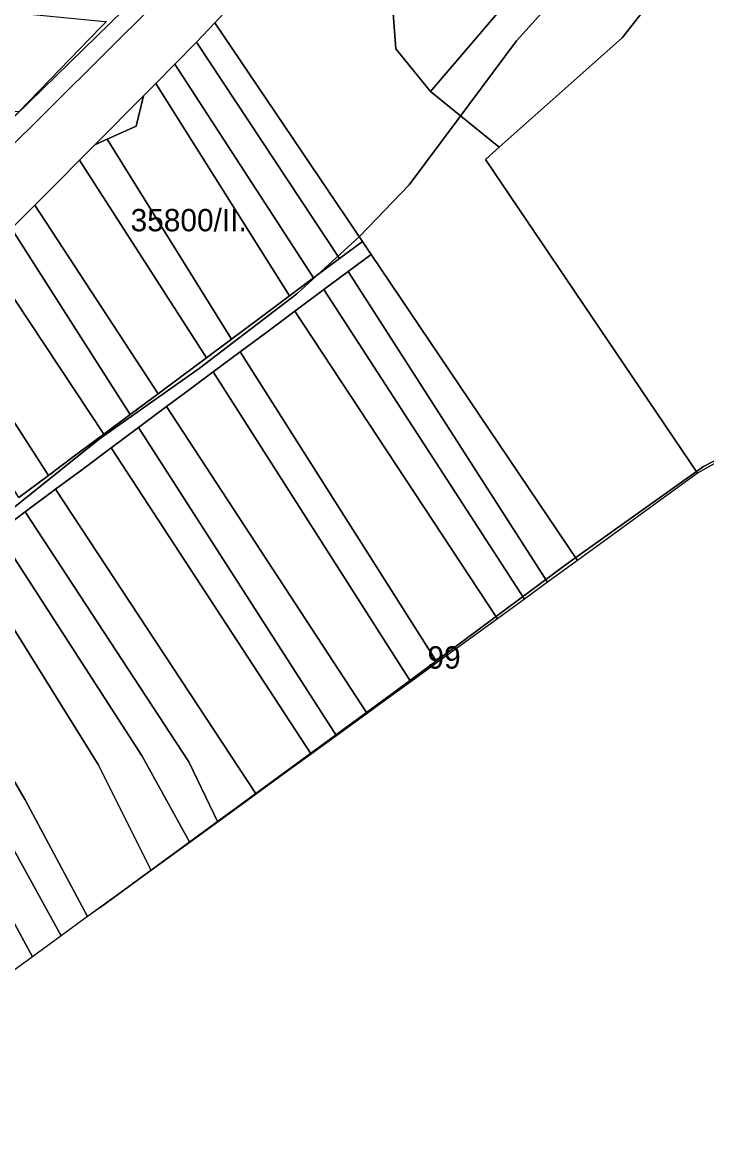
# Model space of a CAD drawing. Extents: x -535894 to -532834, y -1165802 to -1163645.
# Drawn here: x -534096.6 to -533943.2, y -1165431.5 to -1165184 of the extents above; entities that cross this region are included whole.
import ezdxf

# ---------------------------------------------------------------- set-up
doc = ezdxf.new("R2010")
doc.units = 0
for name, color, linetype in [('95560013', 7, 'Continuous'), ('95610013', 7, 'Continuous'), ('95630013', 7, 'Continuous'), ('95640013', 7, 'Continuous'), ('95660013', 7, 'Continuous')]:
    doc.layers.add(name, color=color, linetype=linetype)

msp = doc.modelspace()

# ---------------------------------------------------------------- linework, layer by layer
at = {"layer": '95560013'}
for points in [[(-534196.09, -1165177.34), (-534144.9, -1165178.54), (-534107.5, -1165181.08), (-534103.37, -1165181.48), (-534078.8, -1165183.83), (-534077.66, -1165183.91), (-534078.91, -1165185.19), (-534097.29, -1165204.09), (-534111.65, -1165203.25), (-534176.94, -1165199.42), (-534196.74, -1165197.75)], [(-534053.42, -1165184.18), (-534020.37, -1165233.16), (-534025.49, -1165236.98), (-534057.5, -1165188.56)], [(-534057.5, -1165188.56), (-534025.49, -1165236.98), (-534031.31, -1165241.3), (-534062.36, -1165193.44)], [(-534062.36, -1165193.44), (-534031.31, -1165241.3), (-534036.68, -1165245.31), (-534066.63, -1165197.75)], [(-534066.63, -1165197.75), (-534036.68, -1165245.31), (-534043.59, -1165250.46), (-534049.71, -1165255.01), (-534077.55, -1165210.26), (-534071.03, -1165207.31), (-534069.42, -1165200.54)], [(-534071.03, -1165207.31), (-534077.55, -1165210.26), (-534080.31, -1165211.51), (-534069.42, -1165200.54)], [(-534080.31, -1165211.51), (-534077.55, -1165210.26), (-534049.71, -1165255.01), (-534055.31, -1165259.18), (-534083.69, -1165214.91)], [(-534083.69, -1165214.91), (-534055.31, -1165259.18), (-534060.78, -1165263.26), (-534066.12, -1165267.23), (-534093.73, -1165225.02), (-534088.44, -1165219.7)], [(-534093.73, -1165225.02), (-534066.12, -1165267.23), (-534072.4, -1165271.89), (-534098.91, -1165230.23)], [(-534098.91, -1165230.23), (-534072.4, -1165271.89), (-534078.3, -1165276.29), (-534105.03, -1165235.88)], [(-534105.03, -1165235.88), (-534078.3, -1165276.29), (-534085.13, -1165281.37), (-534090.65, -1165285.49), (-534116.12, -1165246.09), (-534110.88, -1165241.27)], [(-534116.12, -1165246.09), (-534090.65, -1165285.49), (-534097.28, -1165290.43), (-534121.92, -1165251.44)]]:
    msp.add_lwpolyline(points, close=True, dxfattribs=at)
at = {"layer": '95610013'}
for points in [[(-533962.53, -1165085.32), (-533934.45, -1165116.87), (-533940.8, -1165124.3), (-534005.15, -1165199.61), (-534012.92, -1165190.05), (-534014.17, -1165173.12), (-534019.14, -1165162.52), (-534024.54, -1165159.35), (-534021.42, -1165157.14), (-534022.96, -1165151.54), (-534010.91, -1165138.64), (-533976.02, -1165098.2)], [(-533940.8, -1165124.3), (-533927.13, -1165137.47), (-533922.67, -1165144.99), (-533928.42, -1165147.92), (-533942.82, -1165162.9), (-533962.19, -1165187.57), (-533989.71, -1165212.03), (-534005.15, -1165199.61)], [(-534024.54, -1165159.35), (-534019.14, -1165162.52), (-534014.17, -1165173.12), (-534012.92, -1165190.05), (-534005.15, -1165199.61), (-533989.71, -1165212.03), (-533992.77, -1165214.76), (-533945.33, -1165285.03), (-533972.2, -1165304.55), (-534018.44, -1165236.03), (-534020.37, -1165233.16), (-534053.42, -1165184.18), (-534033.26, -1165162.58), (-534030.52, -1165163.57)], [(-533962.19, -1165187.57), (-533942.82, -1165162.9), (-533914.6, -1165207.64), (-533885.93, -1165251.42), (-533945.33, -1165285.03), (-533992.77, -1165214.76), (-533989.71, -1165212.03)], [(-534018.44, -1165236.03), (-533972.2, -1165304.55), (-533978.9, -1165309.42), (-534023.58, -1165239.87)], [(-534023.58, -1165239.87), (-533978.9, -1165309.42), (-533984.1, -1165313.19), (-534028.98, -1165243.88)], [(-534028.98, -1165243.88), (-533984.1, -1165313.19), (-533990.15, -1165317.59), (-534035.47, -1165248.71)], [(-534035.47, -1165248.71), (-533990.15, -1165317.59), (-533996.63, -1165322.3), (-534003.61, -1165327.37), (-534047.73, -1165257.84), (-534041.8, -1165253.42)], [(-534047.73, -1165257.84), (-534003.61, -1165327.37), (-534009.54, -1165331.68), (-534053.75, -1165262.31)], [(-534053.75, -1165262.31), (-534009.54, -1165331.68), (-534014.32, -1165335.17), (-534019.31, -1165338.8), (-534064.21, -1165270.09), (-534058.84, -1165266.1)], [(-534064.21, -1165270.09), (-534019.31, -1165338.8), (-534026.18, -1165343.78), (-534070.53, -1165274.8)], [(-534070.53, -1165274.8), (-534026.18, -1165343.78), (-534031.82, -1165347.88), (-534076.64, -1165279.34)], [(-534076.64, -1165279.34), (-534031.82, -1165347.88), (-534037.71, -1165352.16), (-534044.14, -1165356.83), (-534089.06, -1165288.58), (-534083, -1165284.08)], [(-534089.06, -1165288.58), (-534044.14, -1165356.83), (-534052.73, -1165363.08), (-534059.26, -1165349.61), (-534095.86, -1165293.64)], [(-534095.86, -1165293.64), (-534059.26, -1165349.61), (-534052.73, -1165363.08), (-534059.04, -1165367.66), (-534069.65, -1165348.37), (-534102.06, -1165298.25)], [(-534102.06, -1165298.25), (-534069.65, -1165348.37), (-534059.04, -1165367.66), (-534067.65, -1165373.91), (-534079.55, -1165350.17), (-534108.76, -1165303.24)], [(-534108.76, -1165303.24), (-534079.55, -1165350.17), (-534067.65, -1165373.91), (-534075.22, -1165379.41), (-534081.89, -1165384.25), (-534095.85, -1165358.13), (-534121.89, -1165313.8), (-534115.44, -1165308.22)], [(-534128.01, -1165319.11), (-534121.89, -1165313.8), (-534095.85, -1165358.13), (-534081.89, -1165384.25), (-534087.82, -1165388.56), (-534103.02, -1165361.05)], [(-534134.26, -1165324.52), (-534128.01, -1165319.11), (-534103.02, -1165361.05), (-534087.82, -1165388.56), (-534094.23, -1165393.22), (-534108.57, -1165366.89)], [(-534140.55, -1165329.98), (-534134.26, -1165324.52), (-534108.57, -1165366.89), (-534094.23, -1165393.22), (-534100.32, -1165397.66)]]:
    msp.add_lwpolyline(points, close=True, dxfattribs=at)
at = {"layer": '95630013'}
for points in [[(-534033.26, -1165162.58), (-534053.42, -1165184.18), (-534057.5, -1165188.56), (-534062.36, -1165193.44), (-534066.63, -1165197.75), (-534069.42, -1165200.54), (-534080.31, -1165211.51), (-534083.69, -1165214.91), (-534088.44, -1165219.7), (-534093.73, -1165225.02), (-534098.91, -1165230.23)], [(-534136.8, -1165249.37), (-534066.72, -1165179.82)]]:
    msp.add_lwpolyline(points, dxfattribs=at)
at = {"layer": '95640013'}
for points in [[(-534066.72, -1165179.82), (-534136.8, -1165249.37), (-534194.29, -1165306.12), (-534200.89, -1165312.54), (-534205.31, -1165316.61), (-534215.14, -1165313.24), (-534244.31, -1165303.28), (-534241.33, -1165297.17), (-534240.88, -1165296.25), (-534228.15, -1165300.5), (-534203.98, -1165308.56), (-534201.96, -1165306.58), (-534145.83, -1165251.25), (-534131.84, -1165237.61), (-534110.19, -1165216.6), (-534097.29, -1165204.09), (-534078.91, -1165185.19), (-534077.66, -1165183.91)], [(-534097.28, -1165290.43), (-534090.65, -1165285.49), (-534085.13, -1165281.37), (-534078.3, -1165276.29), (-534072.4, -1165271.89), (-534066.12, -1165267.23), (-534060.78, -1165263.26), (-534055.31, -1165259.18), (-534049.71, -1165255.01), (-534043.59, -1165250.46), (-534036.68, -1165245.31), (-534031.31, -1165241.3), (-534025.49, -1165236.98), (-534020.37, -1165233.16), (-534018.44, -1165236.03), (-534023.58, -1165239.87), (-534028.98, -1165243.88), (-534035.47, -1165248.71), (-534041.8, -1165253.42), (-534047.73, -1165257.84), (-534053.75, -1165262.31), (-534058.84, -1165266.1), (-534064.21, -1165270.09), (-534070.53, -1165274.8), (-534076.64, -1165279.34), (-534083, -1165284.08), (-534089.06, -1165288.58), (-534095.86, -1165293.64), (-534102.06, -1165298.25)]]:
    msp.add_lwpolyline(points, dxfattribs=at)
at = {"layer": '95660013'}
for points in [[(-534504, -1165364.91), (-534479.15, -1165348.82), (-534459.071, -1165335.819), (-534440.92, -1165327.96), (-534400.789, -1165317.92), (-534366.86, -1165313.619), (-534340.91, -1165310.331), (-534288.01, -1165303.627), (-534259.201, -1165299.977), (-534247.08, -1165300.4), (-534235.298, -1165303.278), (-534220.661, -1165306.853), (-534211.72, -1165306.77), (-534205.67, -1165305.18), (-534198.42, -1165301.519), (-534191.96, -1165296.599), (-534183.05, -1165287.34), (-534159.56, -1165262.93), (-534128.66, -1165234.701), (-534052.52, -1165160.48), (-533990.56, -1165093.1), (-533942.78, -1165048.02)], [(-534052.52, -1165160.48), (-534128.66, -1165234.701)], [(-534105.4, -1165298.17), (-534079.332, -1165277.377), (-534075.955, -1165274.993), (-534056.9, -1165261.54), (-534035.084, -1165244.865), (-534020.91, -1165231.99), (-534009.91, -1165220.44), (-533999.16, -1165206.031), (-533985.872, -1165188.218), (-533970.41, -1165171.07)], [(-533970.41, -1165171.07), (-533985.872, -1165188.218), (-533999.16, -1165206.031), (-534009.91, -1165220.44), (-534020.91, -1165231.99), (-534035.084, -1165244.865), (-534056.9, -1165261.54), (-534075.955, -1165274.993), (-534079.332, -1165277.377), (-534105.4, -1165298.17)], [(-533928.089, -1165275.274), (-533943.99, -1165283.5), (-533974.66, -1165305.36), (-534013.02, -1165333.89), (-534079.092, -1165382.22), (-534081.89, -1165384.25), (-534087.82, -1165388.56), (-534094.23, -1165393.22), (-534100.32, -1165397.66), (-534105.93, -1165402.64), (-534112, -1165409.73), (-534115, -1165414.12), (-534119.41, -1165420.59), (-534123.86, -1165427.13), (-534126.75, -1165433.55)]]:
    msp.add_lwpolyline(points, dxfattribs=at)
msp.add_lwpolyline([(-534075.22, -1165379.41), (-534079.092, -1165382.22), (-534013.02, -1165333.89), (-533974.66, -1165305.36), (-533943.99, -1165283.5), (-533928.089, -1165275.274), (-533945.33, -1165285.03), (-533972.2, -1165304.55), (-533978.9, -1165309.42), (-533984.1, -1165313.19), (-533990.15, -1165317.59), (-533996.63, -1165322.3), (-534003.61, -1165327.37), (-534009.54, -1165331.68), (-534014.32, -1165335.17), (-534019.31, -1165338.8), (-534026.18, -1165343.78), (-534031.82, -1165347.88), (-534037.71, -1165352.16), (-534044.14, -1165356.83), (-534052.73, -1165363.08), (-534059.04, -1165367.66), (-534067.65, -1165373.91)], close=True, dxfattribs=at)

# ---------------------------------------------------------------- texts
for s, rotation, p in [('35800/II.', 0, (-534072.282, -1165230.865)), ('99', 360, (-534005.805, -1165328.747))]:
    msp.add_text(s, height=5, rotation=rotation, dxfattribs=at).set_placement(p)

doc.saveas('drawing.dxf')
